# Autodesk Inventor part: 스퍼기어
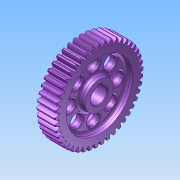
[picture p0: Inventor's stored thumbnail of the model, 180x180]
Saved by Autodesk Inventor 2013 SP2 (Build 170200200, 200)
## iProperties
Created: 2025-05
Part Number: 스퍼기어
Material: Generic
Document SubType Name: Modeling
Designer: a
Density: 1 g/cm^3
Author: a
변환 표준: STEP AP214IS
전처리기: Build: 200, Release: 2013 SP2 Update 6 - Date: Thu 07/17/2014
전송 단위: 밀리미터
불확실성: 0.01
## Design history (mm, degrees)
node "스퍼기어1"
node "솔리드1"
node "기준1"
